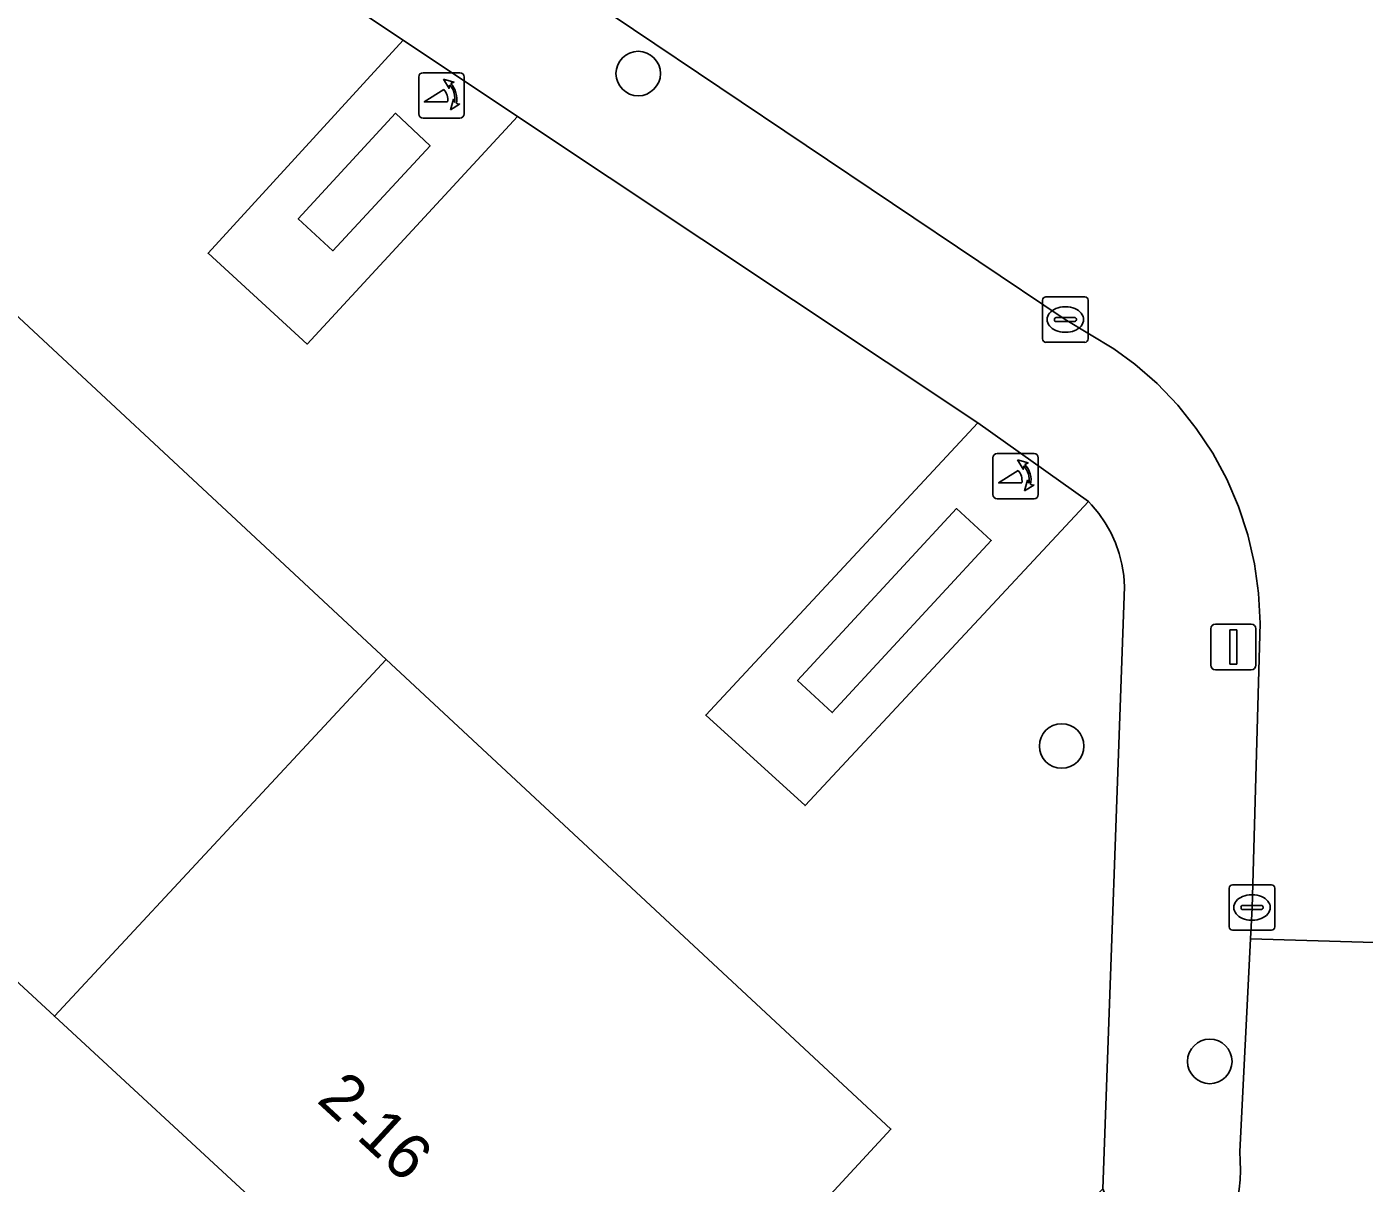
# Model space of a CAD drawing. Extents: x 159217 to 160349, y 381246 to 382172.
# Drawn here: x 159909.62 to 159939.01, y 381826.46 to 381851.88 of the extents above; entities that cross this region are included whole.
import ezdxf

# ---------------------------------------------------------------- set-up
doc = ezdxf.new("R2010")
doc.units = 0
for name, color, linetype in [('IMGEO_Boom', 7, 'Continuous'), ('IMGEO_Erf', 7, 'Continuous'), ('IMGEO_Groenvoorziening', 7, 'Continuous'), ('IMGEO_Kolk', 7, 'Continuous'), ('IMGEO_Lichtmast', 7, 'Continuous'), ('IMGEO_Pand', 7, 'Continuous'), ('IMGEO_Pand_nummerreeks', 7, 'Continuous'), ('IMGEO_Poller', 7, 'Continuous'), ('IMGEO_Rijbaan_lokaal_gesloten', 7, 'Continuous'), ('IMGEO_Rijbaan_lokaal_open', 7, 'Continuous'), ('IMGEO_Voetpad_open', 7, 'Continuous')]:
    doc.layers.add(name, color=color, linetype=linetype)

msp = doc.modelspace()

# ---------------------------------------------------------------- linework, layer by layer
at = {"layer": 'IMGEO_Boom'}
for centre in [(159923.053, 381850.851), (159932.358, 381836.072), (159935.614, 381829.14)]:
    msp.add_circle(centre, 0.489, dxfattribs=at)
at = {"layer": 'IMGEO_Erf'}
for points in [[(159920.4, 381849.909), (159917.884, 381851.585), (159913.6, 381846.901), (159915.779, 381844.906)], [(159915.582, 381847.661), (159917.721, 381849.977), (159918.479, 381849.264), (159916.344, 381846.958)], [(159932.947, 381841.446), (159930.515, 381843.175), (159924.539, 381836.75), (159926.719, 381834.762)], [(159926.557, 381837.51), (159930.05, 381841.29), (159930.811, 381840.588), (159927.318, 381836.808)]]:
    msp.add_lwpolyline(points, close=True, dxfattribs=at)
at = {"layer": 'IMGEO_Groenvoorziening'}
msp.add_lwpolyline([(159906.57, 381848.156), (159917.516, 381837.973), (159928.608, 381827.654), (159921.379, 381819.838), (159924.084, 381817.44), (159933.265, 381826.34), (159933.739, 381839.573), (159933.722, 381839.82), (159933.683, 381840.065), (159933.622, 381840.305), (159933.54, 381840.539), (159933.438, 381840.764), (159933.315, 381840.98), (159933.174, 381841.183), (159933.016, 381841.373), (159932.947, 381841.446), (159926.719, 381834.762), (159924.539, 381836.75), (159930.515, 381843.175), (159920.4, 381849.909), (159915.779, 381844.906), (159913.6, 381846.901), (159917.884, 381851.585), (159907.763, 381858.313)], dxfattribs=at)
for points in [[(159918.479, 381849.264), (159917.721, 381849.977), (159915.582, 381847.661), (159916.344, 381846.958)], [(159930.811, 381840.588), (159930.05, 381841.29), (159926.557, 381837.51), (159927.318, 381836.808)]]:
    msp.add_lwpolyline(points, close=True, dxfattribs=at)
at = {"layer": 'IMGEO_Kolk'}
for p, q in [((159932.014, 381845.944), (159932.866, 381845.944)), ((159931.939, 381845.018), (159931.939, 381845.87)), ((159932.427, 381845.724), (159932.452, 381845.724)), ((159932.94, 381845.87), (159932.94, 381845.018)), ((159932.198, 381845.438), (159932.198, 381845.45)), ((159932.636, 381845.401), (159932.238, 381845.401)), ((159932.241, 381845.487), (159932.639, 381845.487)), ((159932.682, 381845.45), (159932.682, 381845.438)), ((159932.45, 381845.164), (159932.425, 381845.164)), ((159932.866, 381844.944), (159932.014, 381844.944)), ((159936.116, 381833.023), (159936.968, 381833.023)), ((159936.041, 381832.097), (159936.041, 381832.949)), ((159936.529, 381832.803), (159936.554, 381832.803)), ((159937.042, 381832.949), (159937.042, 381832.097)), ((159936.3, 381832.517), (159936.3, 381832.529)), ((159936.738, 381832.48), (159936.34, 381832.48)), ((159936.343, 381832.566), (159936.741, 381832.566)), ((159936.784, 381832.529), (159936.784, 381832.517)), ((159936.552, 381832.243), (159936.527, 381832.243)), ((159936.968, 381832.023), (159936.116, 381832.023))]:
    msp.add_line(p, q, dxfattribs=at)
for points in [[(159932.014, 381845.944), (159932.866, 381845.944)], [(159931.939, 381845.018), (159931.939, 381845.87)], [(159932.94, 381845.87), (159932.94, 381845.018)], [(159932.866, 381844.944), (159932.014, 381844.944)], [(159936.116, 381833.023), (159936.968, 381833.023)], [(159936.041, 381832.097), (159936.041, 381832.949)], [(159937.042, 381832.949), (159937.042, 381832.097)], [(159936.968, 381832.023), (159936.116, 381832.023)]]:
    msp.add_lwpolyline(points, dxfattribs=at)
for centre, radius, start, end in [((159932.016, 381845.868), 0.0765, 91.552, 178.448), ((159932.016, 381845.868), 0.0765, 91.552, 178.448), ((159932.864, 381845.868), 0.0765, 1.552, 88.448), ((159932.864, 381845.868), 0.0765, 1.552, 88.448), ((159932.238, 381845.447), 0.0403, 85.8775, 175.7526), ((159932.235, 381845.437), 0.0366, 178.938, 274.7102), ((159932.639, 381845.444), 0.043, 264.8664, 352.4533), ((159932.643, 381845.449), 0.0386, 1.7309, 96.639), ((159932.016, 381845.02), 0.0765, 181.552, 268.448), ((159932.016, 381845.02), 0.0765, 181.552, 268.448), ((159932.864, 381845.02), 0.0765, 271.552, 358.448), ((159932.864, 381845.02), 0.0765, 271.552, 358.448), ((159936.118, 381832.947), 0.0765, 91.552, 178.448), ((159936.118, 381832.947), 0.0765, 91.552, 178.448), ((159936.966, 381832.947), 0.0765, 1.552, 88.448), ((159936.966, 381832.947), 0.0765, 1.552, 88.448), ((159936.34, 381832.526), 0.0403, 85.8775, 175.7526), ((159936.337, 381832.516), 0.0366, 178.938, 274.7102), ((159936.741, 381832.523), 0.043, 264.8664, 352.4533), ((159936.745, 381832.528), 0.0386, 1.7309, 96.639), ((159936.118, 381832.099), 0.0765, 181.552, 268.448), ((159936.118, 381832.099), 0.0765, 181.552, 268.448), ((159936.966, 381832.099), 0.0765, 271.552, 358.448), ((159936.966, 381832.099), 0.0765, 271.552, 358.448)]:
    msp.add_arc(centre, radius, start, end, dxfattribs=at)
for centre, major_axis, ratio, start_param, end_param in [((159932.426, 381845.444), (-0.387, 0.002), 0.722429, 4.712389, 7.853982), ((159932.451, 381845.444), (-0.39, 0.002), 0.717154, 1.570796, 4.712389), ((159936.528, 381832.523), (-0.387, 0.002), 0.722429, 4.712389, 7.853982), ((159936.553, 381832.523), (-0.39, 0.002), 0.717154, 1.570796, 4.712389)]:
    msp.add_ellipse(centre, major_axis=major_axis, ratio=ratio, start_param=start_param, end_param=end_param, dxfattribs=at)
at = {"layer": 'IMGEO_Lichtmast'}
for p, q in [((159935.636, 381837.849), (159935.636, 381838.649)), ((159935.636, 381838.649), (159935.636, 381837.849)), ((159935.736, 381838.749), (159936.526, 381838.749)), ((159936.526, 381838.749), (159935.736, 381838.749)), ((159936.626, 381838.649), (159936.626, 381837.849)), ((159936.626, 381837.849), (159936.626, 381838.649)), ((159936.526, 381837.749), (159935.736, 381837.749)), ((159935.736, 381837.749), (159936.526, 381837.749))]:
    msp.add_line(p, q, dxfattribs=at)
msp.add_lwpolyline([(159936.056, 381838.624), (159936.206, 381838.624), (159936.206, 381837.874), (159936.056, 381837.874), (159936.056, 381838.624)], dxfattribs=at)
for centre, start, end in [((159935.736, 381838.649), 90, 180), ((159935.736, 381838.649), 90, 180), ((159936.526, 381838.649), 0, 90), ((159936.526, 381838.649), 360, 90), ((159935.736, 381837.849), 180, 270), ((159935.736, 381837.849), 180, 270), ((159936.526, 381837.849), 270, 0), ((159936.526, 381837.849), 270, 0)]:
    msp.add_arc(centre, 0.1, start, end, dxfattribs=at)
at = {"layer": 'IMGEO_Pand'}
for points in [[(159906.57, 381848.156), (159899.239, 381840.277), (159903.845, 381836.023), (159902.871, 381834.969), (159904.678, 381833.3), (159905.653, 381834.354), (159910.222, 381830.133), (159917.516, 381837.973)], [(159917.516, 381837.973), (159910.222, 381830.133), (159914.791, 381825.913), (159913.815, 381824.858), (159915.659, 381823.155), (159916.633, 381824.21), (159921.379, 381819.838), (159928.608, 381827.654)]]:
    msp.add_lwpolyline(points, close=True, dxfattribs=at)
at = {"layer": 'IMGEO_Poller'}
for p, q in [((159918.23, 381850.775), (159918.23, 381849.968)), ((159918.23, 381850.775), (159918.23, 381849.968)), ((159919.132, 381850.87), (159918.324, 381850.87)), ((159919.132, 381850.87), (159918.324, 381850.87)), ((159919.226, 381849.968), (159919.226, 381850.775)), ((159919.226, 381849.968), (159919.226, 381850.775)), ((159918.324, 381849.873), (159919.132, 381849.873)), ((159918.324, 381849.873), (159919.132, 381849.873)), ((159931.751, 381842.499), (159930.943, 381842.499)), ((159931.751, 381842.499), (159930.943, 381842.499)), ((159930.849, 381842.404), (159930.849, 381841.597)), ((159930.849, 381842.404), (159930.849, 381841.597)), ((159931.845, 381841.597), (159931.845, 381842.404)), ((159931.845, 381841.597), (159931.845, 381842.404)), ((159930.943, 381841.502), (159931.751, 381841.502)), ((159930.943, 381841.502), (159931.751, 381841.502))]:
    msp.add_line(p, q, dxfattribs=at)
for points in [[(159918.909, 381850.599), (159918.897, 381850.526), (159918.772, 381850.731)], [(159918.772, 381850.731), (159919.003, 381850.665), (159918.932, 381850.633)], [(159918.865, 381850.226), (159918.352, 381850.226), (159918.782, 381850.501)], [(159918.925, 381850.054), (159918.991, 381850.285), (159919.021, 381850.217)], [(159919.057, 381850.19), (159919.129, 381850.179), (159918.925, 381850.054)], [(159931.484, 381841.855), (159930.971, 381841.855), (159931.401, 381842.13)], [(159931.528, 381842.228), (159931.516, 381842.155), (159931.391, 381842.36)], [(159931.391, 381842.36), (159931.622, 381842.294), (159931.551, 381842.262)], [(159931.544, 381841.683), (159931.61, 381841.914), (159931.64, 381841.846)], [(159931.676, 381841.819), (159931.748, 381841.808), (159931.544, 381841.683)]]:
    msp.add_lwpolyline(points, dxfattribs=at)
for centre, radius, start, end in [((159918.324, 381850.775), 0.0946, 90, 180), ((159918.324, 381850.775), 0.0946, 90, 180), ((159919.132, 381850.775), 0.0946, 0, 90), ((159919.132, 381850.775), 0.0946, 0, 90), ((159918.537, 381850.276), 0.332, 351.3247, 42.4854), ((159918.551, 381850.286), 0.476, 351.7527, 41.1691), ((159918.551, 381850.286), 0.516, 349.3569, 42.2912), ((159918.324, 381849.968), 0.0946, 180, 270), ((159918.324, 381849.968), 0.0946, 180, 270), ((159919.132, 381849.968), 0.0946, 270, 0), ((159919.132, 381849.968), 0.0946, 270, 0), ((159930.943, 381842.404), 0.0946, 90, 180), ((159930.943, 381842.404), 0.0946, 90, 180), ((159931.751, 381842.404), 0.0946, 0, 90), ((159931.751, 381842.404), 0.0946, 0, 90), ((159931.156, 381841.905), 0.332, 351.3247, 42.4854), ((159931.17, 381841.915), 0.476, 351.7527, 41.1691), ((159931.17, 381841.915), 0.516, 349.3569, 42.2912), ((159930.943, 381841.597), 0.0946, 180, 270), ((159930.943, 381841.597), 0.0946, 180, 270), ((159931.751, 381841.597), 0.0946, 270, 0), ((159931.751, 381841.597), 0.0946, 270, 0)]:
    msp.add_arc(centre, radius, start, end, dxfattribs=at)
at = {"layer": 'IMGEO_Rijbaan_lokaal_gesloten'}
msp.add_lwpolyline([(159937.597, 381852.913), (159925.548, 381861.046), (159922.012, 381863.423), (159918.533, 381865.684), (159913.46, 381858.201), (159932.433, 381845.449), (159933.505, 381844.804), (159933.966, 381844.465), (159934.458, 381844.036), (159934.91, 381843.564), (159935.318, 381843.053), (159935.679, 381842.508), (159935.989, 381841.933), (159936.247, 381841.333), (159936.451, 381840.712), (159936.598, 381840.075), (159936.688, 381839.428), (159936.719, 381838.775), (159936.543, 381832.512), (159936.509, 381831.835), (159941.711, 381831.68), (159942.042, 381839.799)], dxfattribs=at)
at = {"layer": 'IMGEO_Rijbaan_lokaal_open'}
msp.add_lwpolyline([(159941.675, 381830.784), (159941.711, 381831.68), (159936.509, 381831.835), (159936.272, 381827.161)], dxfattribs=at)
msp.add_arc((159932.121, 381826.796), 4.167, 319.5285, 5.0296, dxfattribs=at)
at = {"layer": 'IMGEO_Voetpad_open'}
for points in [[(159936.272, 381827.161), (159936.509, 381831.835), (159936.543, 381832.512), (159936.719, 381838.775), (159936.688, 381839.428), (159936.598, 381840.075), (159936.451, 381840.712), (159936.247, 381841.333), (159935.989, 381841.933), (159935.679, 381842.508), (159935.318, 381843.053), (159934.91, 381843.564), (159934.458, 381844.036), (159933.966, 381844.465), (159933.505, 381844.804), (159932.433, 381845.449), (159913.46, 381858.201), (159909.287, 381860.934), (159903.453, 381864.809)], [(159907.763, 381858.313), (159917.884, 381851.585), (159920.4, 381849.909), (159930.515, 381843.175), (159932.947, 381841.446), (159933.016, 381841.373), (159933.174, 381841.183), (159933.315, 381840.98), (159933.438, 381840.764), (159933.54, 381840.539), (159933.622, 381840.305), (159933.683, 381840.065), (159933.722, 381839.82), (159933.739, 381839.573), (159933.265, 381826.34), (159934.469, 381823.293), (159935.291, 381824.091)], [(159884.869, 381848.657), (159899.927, 381834.749), (159921.488, 381814.881), (159924.084, 381817.44), (159921.379, 381819.838), (159916.633, 381824.21), (159915.659, 381823.155), (159913.815, 381824.858), (159914.791, 381825.913), (159910.222, 381830.133), (159905.653, 381834.354)]]:
    msp.add_lwpolyline(points, dxfattribs=at)
msp.add_arc((159932.121, 381826.796), 4.167, 319.5285, 5.0296, dxfattribs=at)

# ---------------------------------------------------------------- texts
at = {"layer": 'IMGEO_Pand_nummerreeks'}
msp.add_text('2-16', height=1, rotation=317.2997, dxfattribs=at).set_placement((159915.964, 381828.264))

doc.saveas('drawing.dxf')
